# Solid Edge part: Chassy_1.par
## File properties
Author: KULL
Template: Iso Metric Part.par
Last saved by: KULL
Revision: 42
Application: Solid Edge
Accuracy: 0,990
Face Style: Model Default
Fill Style: Normal
Coef. of Thermal Exp: 0.0
Thermal Conductivity: 0.0
Specific Heat: 0.0
Modulus of Elasticity: 0.0
Poisson's Ratio: 0.0
Yield Stress: 0.0
Ultimate Stress: 0.0
Elongation: 0.0
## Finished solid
Body 1: solid body, 1481 faces, 3621 edges, 2108 vertices.
  Faces by surface: cylinder 672, torus 502, plane 231, blend 64, spline 12
  Edges by curve: circle 1960, line 1303, intersection 305, ellipse 32, spline 16, curve on surface 5
Bounding box of the edges (mm; curved faces can reach further): 462.561 x 108.092 x 68.811, from (-402.5106, -54.0462, -7) to (60.0506, 54.0462, 61.811).
Cylindrical faces by radius (mm): R0.4 x168, R0.6 x6, R0.704 x4, R1 x190, R1.704 x8, R2 x64, R2.4738 x8, R2.5 x16, R2.8293 x8, R3 x8, R3.0279 x8, R3.0577 x8, R3.5785 x8, R3.7473 x8, R4 x34, R4.0337 x8, R5 x26, R6 x24, R7 x8, R7.1013 x8, R10 x8, R17 x8, R23 x8, R30.2927 x4, R33.2927 x8, R77.9693 x8, R80.9693 x8
Toroidal faces (ring radius, tube radius in mm): R1.4 r1 x16, R2 r1 x8, R2.104 r0.4 x16, R2.4293 r0.4 x16, R2.8738 r0.4 x16, R3 r1 x48, R3.4 r0.4 x16, R3.4279 r0.4 x16, R3.4577 r0.4 x16, R3.6 r0.4 x48, R3.9785 r0.4 x16, R4 r1 x16, R4 r2 x16, R4.1473 r0.4 x16, R4.4337 r0.4 x16, R4.6 r0.4 x32, R5 r1 x8, R5.6 r0.6 x6, R7 r1 x8, R7.5013 r0.4 x16, R8 r1 x16, R8 r2 x16, R9.6 r0.4 x16, R17.4 r0.4 x16, R22.6 r0.4 x16, R30.6927 r0.4 x8, R32.8927 r0.4 x16, R78.3693 r0.4 x16, R80.5693 r0.4 x16
Planar faces by outward normal: +x 35, +y 17, +z 37, -x 39, -y 16, -z 16, oblique 71
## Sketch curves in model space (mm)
circle centre (-169.23, 9, 15.2131) radius 5
circle centre (-169.23, -9, 15.2131) radius 5
circle centre (-169.23, 9, 15.2131) radius 6
circle centre (-169.23, -9, 15.2131) radius 6
line (15, 37.1856, 4.6472) -> (15, 37.1856, 4.5)
circle centre (15, 45, 56.811) radius 2.5
line (-36, 45, 5.8069) -> (-36, 45, 5.811)
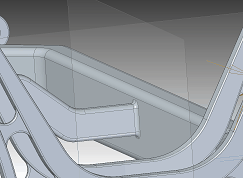
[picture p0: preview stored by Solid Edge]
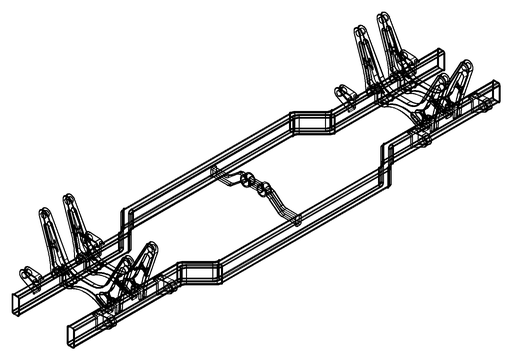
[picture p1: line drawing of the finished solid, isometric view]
